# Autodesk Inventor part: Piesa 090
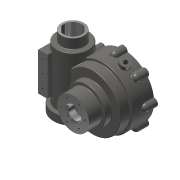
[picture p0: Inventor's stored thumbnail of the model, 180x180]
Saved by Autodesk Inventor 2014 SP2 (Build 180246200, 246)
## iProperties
Created: 2009-02
Part Number: Piesa 090
Document SubType Name: Modeling
Designer: Costel
Material: Steel, Cast
Density: 7.85 g/cm^3
Appearance: Steel - Cast
Mass: 18295 g
Surface Area: 3153.98 cm^2
Volume: 2330.57 cm^3
Author: Costel
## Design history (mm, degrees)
sketch "Sketch1"
  geometry: L1 (0, -99)-(50, -99); L2 (50, -99)-(50, -58); L3 (50, -58)-(60, -58); L4 (60, -58)-(60, -38); L5 (60, -38)-(87.5, -38); L6 (87.5, -38)-(87.5, -8); L7 (87.5, -8)-(95, -8); L8 (95, -8)-(95, 60); L9 (95, 60)-(0, 60); L10 (-9.5, 0)-(123.5, 0) reference; L11 (0, -114.9)-(0, 107.7) reference; L12 (0, 60)-(0, -99)
  constraints: 20 end point, 2 point on line, 1 collinear
  dimensions: "d1" = 60 distance between parallel lines of L10 L9; "d7" = 190 diameter of L8 L11; "d8" = 175 diameter of L6 L11; "d9" = 120 diameter of L4 L11; "d10" = 100 diameter of L2 L11; "d15" = 159 distance between parallel lines of L9 L1; "d17" = 41 distance between parallel lines of L1 L3; "d18" = 61 distance between parallel lines of L1 L5; "d19" = 68 distance between parallel lines of L9 L7
revolve "Revolution1" sketch "Sketch1" stored, may be unused: angle "d29" = 90 deg
sketch "Sketch2"
  geometry: L1 (114, 0)-(-152, 0) reference; L2 (0, -114)-(0, 152) reference; L3 (100, 130)-(100, -90); L4 (160, -90)-(100, -90); L5 (135, 130)-(100, 130); L6 (135, 130)-(135, 100); L7 (135, 100)-(150, 100); L8 (150, 100)-(150, -65); L9 (150, -65)-(160, -65); L10 (160, -65)-(160, -90)
  constraints: 16 end point, 5 parallel, 3 perpendicular
  dimensions: "d30" = 100 distance between parallel lines of L2 L3; "d31" = 90 distance between parallel lines of L1 L4; "d32" = 220 distance between parallel lines of L5 L4; "d33" = 70 diameter of L6 L3; "d34" = 30 distance between parallel lines of L5 L7; "d35" = 25 distance of L9.end L4.start; "d36" = 100 diameter of L8 L3; "d37" = 120 diameter of L10 L3
revolve "Revolution2" sketch "Sketch2" stored, may be unused: angle "d38" = 90 deg
sketch "Sketch3"
  geometry: L1 (0, -114.9)-(0, 107.7) reference; L2 (-95, 60)-(95, 60) reference; L3 (-50, -99)-(50, -99) reference; L4 (65, 60)-(65, 35); L5 (65, 35)-(82.5, 35); L6 (82.5, 35)-(82.5, 4.5); L7 (82.5, 4.5)-(75, 4.5); L8 (75, 4.5)-(75, -20); L9 (75, -20)-(44.987, -20); L10 (44.987, -20)-(40, 0); L11 (40, 0)-(20, 0); L12 (20, 0)-(20, -30); L13 (20, -30)-(35, -30); L14 (35, -30)-(35, -75); L15 (35, -75)-(20, -75); L16 (20, -75)-(20, -99); L17 (65, 60)-(0, 60); L18 (0, 60)-(0, -99); L19 (0, -99)-(20, -99)
  constraints: 32 end point, 7 perpendicular, 6 parallel, 2 midpoint, 2 point on line
  dimensions: "d39" = 14 deg angle of L8 L10; "d40" = 25 distance of L4.start L4.end; "d41" = 55 distance between parallel lines of L5 L9; "d42" = 24 distance between parallel lines of L19 L15; "d43" = 45 distance between parallel lines of L15 L13; "d44" = 130 diameter of L4 L1; "d45" = 165 diameter of L6 L1; "d46" = 150 diameter of L8 L1; "d47" = 30.5 distance between parallel lines of L5 L7; "d48" = 20 distance between parallel lines of L9 L11; "d49" = 80 diameter of L10.end L1; "d50" = 40 diameter of L12 L1; "d51" = 40 diameter of L16 L1 (= d50); "d52" = 70 diameter of L14 L1
revolve "Revolution3" sketch "Sketch3" stored, may be unused: angle "d53" = 90 deg
sketch "Sketch4"
  geometry: L1 (-185.5, 0)-(171.5, 0) reference; C1 r 65 at (0, 0) reference; A1 r 95 centre (0, 0) between (94.242, 11.976) and (94.242, -11.976) reference; A2 r 12 centre (95, 0) between (94.242, -11.976) and (94.242, 11.976); A3 r 95 centre (0, 0) between (94.242, -11.976) and (94.242, 11.976)
  constraints: 6 point on circle, 2 centre point, 1 coincident, 1 point on line
  dimensions: "d54" = 12 radius of A2; "d55" = 95 distance of C1.centre A2.centre
extrude "Extrusion1" join sketch "Sketch4" distance "d56" = 28; taper "d57" = 0 deg
sketch "Sketch5"
  geometry: L1 (94.242, 32)-(94.242, 32) reference; L2 (94.242, 60)-(94.242, 32) reference; L3 (94.242, 60)-(94.242, 60) reference; L4 (94.242, 32)-(94.242, 60) reference; L5 (94.242, 32)-(94.242, 32) reference; L6 (94.242, 32)-(94.242, 32) reference; L7 (107, 32)-(94.242, 32) reference; L8 (107, 60)-(107, 32) reference; L9 (95, 32)-(95, -8) reference; L10 (95, 20)-(95, 32); L11 (95, 32)-(107, 32); A1 r 12 centre (95, 32) between (95, 20) and (107, 32)
  constraints: 5 end point, 3 point on circle, 2 collinear, 2 point on line, 1 centre point
  dimensions: "d59" = 12 radius of A1 (= d54)
revolve "Revolution4" sketch "Sketch5" stored, may be unused: angle "d58" = 90 deg
hole "Hole1" diameter "d62" = 6.647; stored, may be unused: countersink angle "d66" = 90 deg, drill point angle "d68" = 118 deg; dims "d63" = 23, "d64" = 4, "d65" = 2, "d67" = 27, "d138" = 10, "d141" = 10
pattern_circular "Circular Pattern1" dims "d70" = 360 deg
sketch "Sketch6"
  geometry: L1 (-186.7, 0)-(187.1, 0) reference; C1 r 20 at (0, 0) reference; 6 further points
  constraints: 1 point on line, 7 other
  dimensions: "d72" = 37.5 distance of C1.centre point (37.5, 0); "d75" = 360 deg dimension on C1.centre point (37.5, 0) (derived)
hole "Hole2" sketch "Sketch6" at (37.5, 0), (18.75, 32.476), (-18.75, 32.476), (-37.5, 0), (-18.75, -32.476), (18.75, -32.476) diameter "d77" = 6.647; stored, may be unused: countersink angle "d81" = 90 deg, drill point angle "d83" = 118 deg; dims "d78" = 14, "d79" = 4, "d80" = 2, "d82" = 18
sketch "Sketch7"
  geometry: L1 (65, 130)-(135, 130) reference; L2 (40, -90)-(160, -90) reference; L3 (100, 130)-(100, -90); L4 (128, 130)-(128, 65); L5 (128, 65)-(135, 65); L6 (135, 65)-(135, 45); L7 (135, 45)-(140, 45); L8 (140, 45)-(140, -65); L9 (140, -65)-(135, -65); L10 (135, -65)-(135, -90); L11 (128, 130)-(100, 130); L12 (135, -90)-(100, -90); 2 further points
  constraints: 20 end point, 6 parallel, 3 perpendicular, 2 midpoint, 2 point on line
  dimensions: "d84" = 80 diameter of L8 L3; "d85" = 70 diameter of L10 L3; "d86" = 70 diameter of L6 L3 (= d85); "d87" = 56 diameter of L4 L3; "d88" = 65 distance between parallel lines of L1 L5; "d89" = 85 distance between parallel lines of L1 L7; "d90" = 25 distance between parallel lines of L12 L9
revolve "Revolution5" sketch "Sketch7" stored, may be unused: angle "d91" = 90 deg
workaxis "Work Axis1"
workplane "Work Plane1"
workplane "Work Plane2"
sketch "Sketch8"
  geometry: L1 (-138.5, -24.2)-(-138.5, 25.799) reference; L2 (36.4, 0)-(-186.2, 0) reference; C1 r 15 at (-103.5, 0)
  constraints: 1 centre point, 1 point on line
  dimensions: "d94" = 35 distance from line of L1 C1.centre; "d95" = 30 diameter of C1
extrude "Extrusion2" join sketch "Sketch8" stored distance "d96" = 28; taper "d97" = 0 deg
hole "Hole3" diameter "d100" = 13.835; stored, may be unused: countersink angle "d104" = 90 deg, drill point angle "d106" = 118 deg; dims "d101" = 6, "d102" = 4, "d103" = 2, "d105" = 18, "d126" = 10, "d127" = 10
workplane "Work Plane3"
sketch "Sketch9"
  geometry: L1 (-150, 80)-(-120, 80); L2 (-120, 80)-(-120, -40); L3 (-120, -40)-(-150, -40); L4 (-150, -40)-(-150, 80); L5 (-150, 100)-(-150, -65) reference; L6 (-160, -90)-(-40, -90) reference
  constraints: 8 end point, 2 parallel, 1 collinear, 1 horizontal, 1 perpendicular
  dimensions: "d108" = 30 distance of L1.start L1.end; "d109" = 50 distance between parallel lines of L6 L3; "d110" = 120 distance between parallel lines of L1 L3
extrude "Extrusion3" join sketch "Sketch9" stored distance "d111" = 28; taper "d112" = 0 deg
sketch "Sketch10"
  geometry: L1 (-150, 80)-(-120, 80) reference; L2 (-120, -40)-(-150, -40) reference; 4 further points
  constraints: 3 vertical alignment, 1 midpoint
  dimensions: "d113" = 40 distance of point (-135, 20) point (-135, -20); "d114" = 20 distance from line of L2 point (-135, -20); "d115" = 40 distance of point (-135, 60) point (-135, 20)
hole "Hole4" sketch "Sketch10" at (-135, -20), (-135, 20), (-135, 60) diameter "d116" = 6.647; stored, may be unused: countersink angle "d120" = 90 deg, drill point angle "d122" = 118 deg; dims "d117" = 20, "d118" = 4, "d119" = 2, "d121" = 25
chamfer "Chamfer1" distance "d123" = 5; stored, may be unused: second distance "d124" = 2, angle "d125" = 45 deg
fillet "Fillet1" dims "d128" = 2
fillet "Fillet2" dims "d129" = 2
fillet "Fillet3" dims "d132" = 2
fillet "Fillet4" dims "d133" = 2
fillet "Fillet5" dims "d134" = 2
fillet "Fillet6" dims "d135" = 2
fillet "Fillet7" dims "d136" = 2
fillet "Fillet8" dims "d137" = 2
chamfer "Chamfer2" distance "d139" = 3; stored, may be unused: second distance "d140" = 2, angle "d142" = 45 deg
body "Solid1"
node "Projected Loop1"
node "Projected Loop2"
other parameters: "d92" = -22 deg, "d93" = 106
